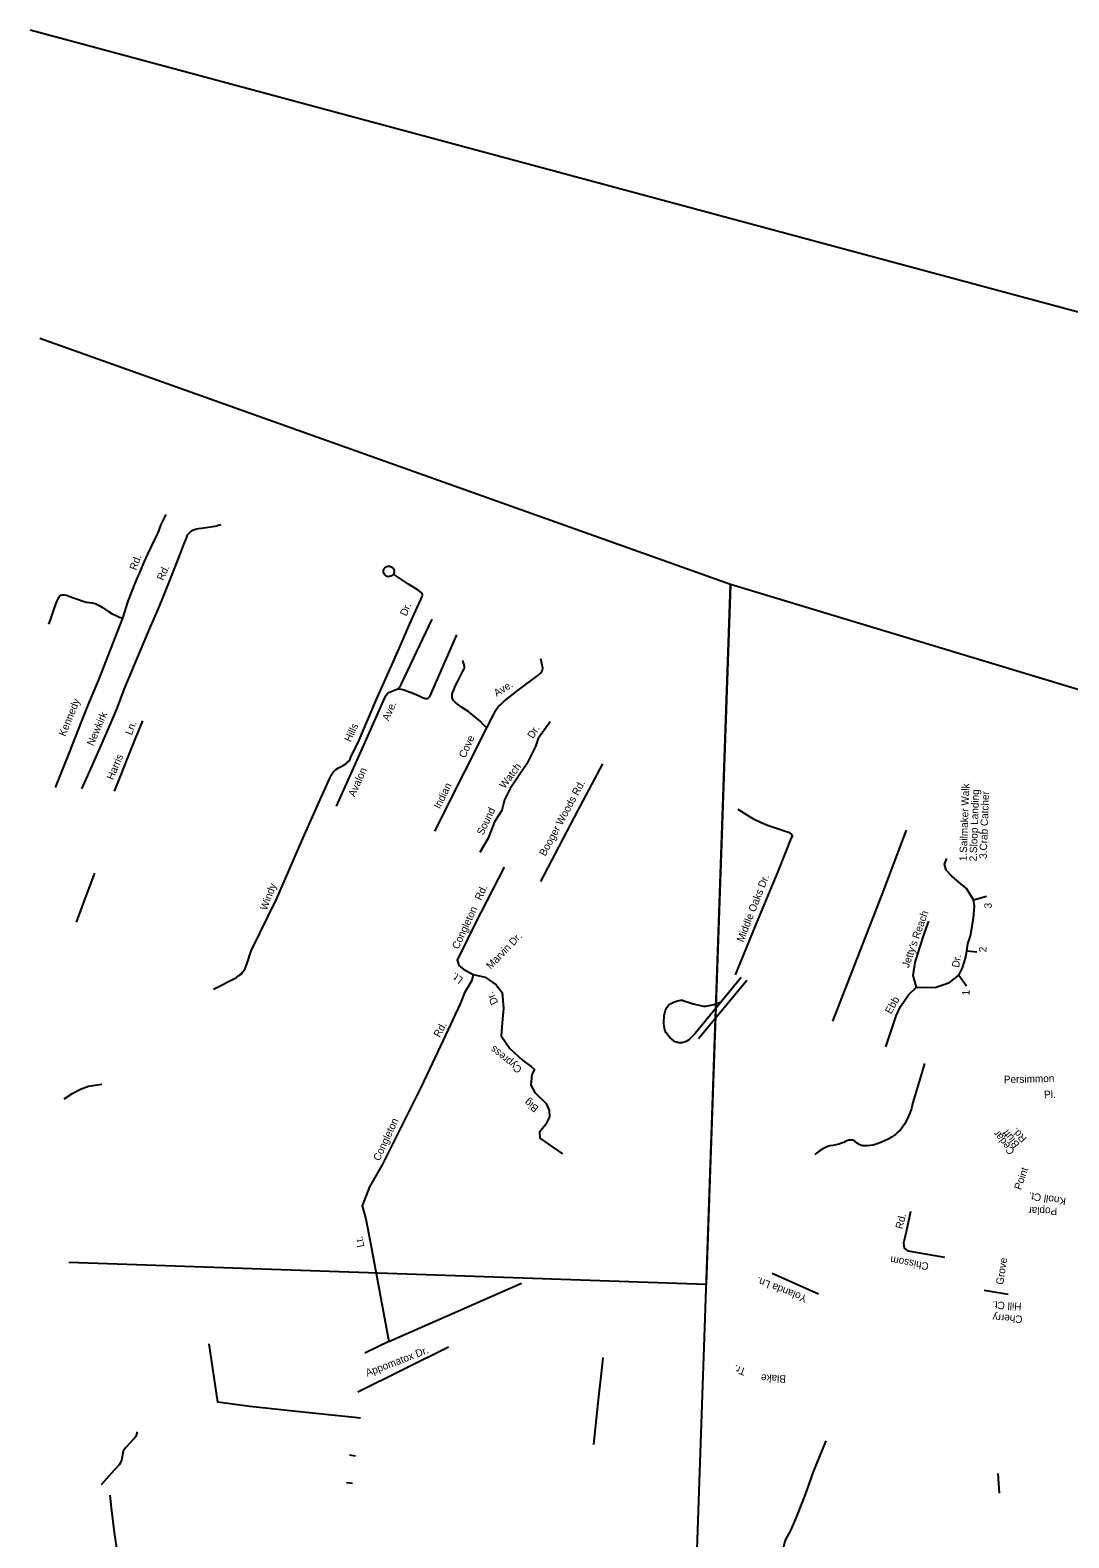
# Model space of a CAD drawing. Extents: x 2308163 to 2335412, y -96774 to 127732.
# Drawn here: x 2320522 to 2321093, y 33932 to 34759 of the extents above; entities that cross this region are included whole.
import ezdxf

# ---------------------------------------------------------------- set-up
doc = ezdxf.new("R2010")
doc.units = 0
for name, color, linetype in [('Old_Level_10', 7, 'Continuous'), ('Old_Level_35', 7, 'Continuous'), ('Old_Level_63', 7, 'Continuous')]:
    doc.layers.add(name, color=color, linetype=linetype)

msp = doc.modelspace()

# ---------------------------------------------------------------- linework, layer by layer
at = {"layer": 'Old_Level_35'}
for p, q in [((2320889.29, 34205.99), (2320915.81, 34237.99)), ((2320912.73, 34239.56), (2320901.77, 34226.2)), ((2320703.76, 33997.64), (2320700.4, 33997.97)), ((2320701, 33976.7), (2320697.76, 33977.28)), ((2321053.71, 33967.28), (2321054.37, 33956.49)), ((2320564.27, 33964.25), (2320561.35, 33961.01)), ((2320699.39, 33961.73), (2320696.15, 33962.06)), ((2320566.04, 33955.37), (2320566.63, 33950.28))]:
    msp.add_line(p, q, dxfattribs=at)
for points in [[(2320550.76, 34343.03), (2320555.7, 34354.07), (2320561.14, 34366.45), (2320566.32, 34378.22), (2320570.42, 34387.76), (2320573.97, 34397.51), (2320584.49, 34422.43), (2320588.52, 34431.96), (2320591.86, 34439.87), (2320594.96, 34447.4), (2320598.32, 34455.56), (2320601.42, 34463.49), (2320605.02, 34472.73), (2320606.74, 34477.1), (2320607.63, 34479.32), (2320608.34, 34481.17), (2320608.84, 34482.4), (2320609.62, 34483.39), (2320610.39, 34484.11), (2320611.66, 34484.96), (2320613.2, 34485.54), (2320614.83, 34485.9), (2320616.49, 34486.11), (2320618.95, 34486.41), (2320621.45, 34486.81), (2320622.7, 34487.06), (2320624.81, 34487.44), (2320625.69, 34487.69), (2320627.33, 34488.15)], [(2320573.27, 34436.76), (2320576.15, 34446.06), (2320579.11, 34453.47), (2320580.85, 34457.56), (2320583.16, 34463.13), (2320585.14, 34467.81), (2320586.9, 34471.9), (2320591, 34480.28), (2320592.61, 34483.51), (2320594.36, 34488.19), (2320597.02, 34493.64)], [(2320721.79, 34460.87), (2320721.38, 34460.35), (2320720.94, 34459.99), (2320720.41, 34459.68), (2320719.74, 34459.5), (2320719.06, 34459.48), (2320718.43, 34459.62), (2320717.93, 34459.84), (2320717.45, 34460.16), (2320717.08, 34460.55), (2320716.76, 34461.02), (2320716.56, 34461.43), (2320716.46, 34461.92), (2320716.41, 34462.42), (2320716.45, 34462.85), (2320716.56, 34463.35), (2320716.77, 34463.76), (2320717.05, 34464.19), (2320717.37, 34464.52), (2320717.74, 34464.83), (2320718.18, 34465.03), (2320718.58, 34465.18), (2320719.15, 34465.28), (2320719.7, 34465.25), (2320720.28, 34465.13), (2320720.72, 34464.93), (2320721.11, 34464.63), (2320721.39, 34464.41), (2320721.68, 34464.06), (2320721.9, 34463.73), (2320722.05, 34463.34), (2320722.16, 34462.91), (2320722.2, 34462.52), (2320722.21, 34462.07), (2320722.13, 34461.67), (2320722.01, 34461.27), (2320721.79, 34460.87)], [(2320680.39, 34334.22), (2320687.02, 34349.29), (2320687.81, 34350.79), (2320688.32, 34351.51), (2320688.82, 34352.25), (2320689.48, 34353), (2320690.25, 34353.72), (2320691.64, 34354.56), (2320694.18, 34355.89), (2320695.69, 34356.72), (2320696.32, 34357.23), (2320697.18, 34358.1), (2320698.01, 34359.41), (2320698.38, 34360.34), (2320702.98, 34369.67), (2320712.16, 34391.34), (2320721.55, 34412.17), (2320726.2, 34422.96), (2320730.68, 34433.24), (2320734.08, 34440.88), (2320736.81, 34447.03), (2320737.54, 34448.52), (2320737.71, 34449.32), (2320737.53, 34450.18), (2320737.07, 34450.75), (2320735.35, 34452.01), (2320730.17, 34455.3), (2320721.79, 34460.87)], [(2320532.65, 34433.41), (2320533.48, 34435.88), (2320535.36, 34441.34), (2320536.45, 34444.42), (2320537.18, 34446.27), (2320537.67, 34447.4), (2320538.18, 34448.27), (2320538.67, 34448.9), (2320539.16, 34449.27), (2320539.79, 34449.52), (2320540.22, 34449.57), (2320541.16, 34449.53), (2320542.41, 34449.29), (2320545.68, 34448.06), (2320549.4, 34446.7), (2320551.39, 34446), (2320553.36, 34445.45), (2320554.98, 34445.3), (2320556.44, 34445.12), (2320558.1, 34444.7), (2320559.21, 34444.29), (2320560.69, 34443.5), (2320562.19, 34442.52), (2320563.16, 34441.79), (2320565.36, 34440.35), (2320567.33, 34439.17), (2320569.55, 34438.11), (2320570.9, 34437.44), (2320573.27, 34436.76)], [(2320536.26, 34343.84), (2320543.91, 34363), (2320550.57, 34379.78), (2320554.91, 34390.79), (2320560.09, 34402.81), (2320573.27, 34436.76)], [(2320724.32, 34397.92), (2320725.12, 34398.8), (2320725.87, 34399.89), (2320726.28, 34400.76), (2320743.08, 34436.1)], [(2320724.32, 34397.92), (2320726.17, 34397.72), (2320727.69, 34397.34), (2320729.56, 34396.67), (2320733.03, 34395.34), (2320735.98, 34394.02), (2320738.22, 34392.94), (2320739.41, 34392.66), (2320740.34, 34392.65), (2320740.91, 34392.83), (2320741.3, 34393.08), (2320741.75, 34393.62), (2320742.13, 34394.36), (2320756.63, 34427.51)], [(2320773.21, 34376.48), (2320771.38, 34378.15), (2320769.42, 34380.09), (2320766.36, 34382.65), (2320763.17, 34385.24), (2320759.24, 34387.95), (2320756.77, 34389.63), (2320755.66, 34390.57), (2320755.06, 34391.31), (2320754.69, 34391.74), (2320754.21, 34392.57), (2320754.11, 34393.19), (2320754, 34393.97), (2320754.16, 34394.95), (2320754.54, 34396.08), (2320755.21, 34397.81), (2320755.78, 34399.3), (2320756.94, 34401.75), (2320758.4, 34404.73), (2320759.82, 34407.32), (2320760.61, 34408.92), (2320760.85, 34409.7), (2320760.89, 34410.42), (2320759.88, 34413.5)], [(2320773.21, 34376.48), (2320776.91, 34384.02), (2320778.08, 34386.24), (2320778.78, 34387.31), (2320779.61, 34388.25), (2320780.92, 34389.55), (2320782.57, 34391.14), (2320789.57, 34396.58), (2320801.05, 34405.33), (2320802.72, 34406.78), (2320803.25, 34407.46), (2320803.74, 34408.26), (2320803.92, 34409.26), (2320802.81, 34414.41)], [(2320690.5, 34333.47), (2320703.33, 34362.04), (2320717.07, 34392.98), (2320717.52, 34393.95), (2320717.8, 34394.36), (2320718.07, 34394.67), (2320718.43, 34395.1), (2320718.88, 34395.55), (2320719.15, 34395.76), (2320719.7, 34396.07), (2320724.32, 34397.92)], [(2320568.76, 34341.75), (2320571.74, 34349.39), (2320576.17, 34360.54), (2320579.87, 34369.68), (2320584.19, 34380.32)], [(2320807.84, 34379.78), (2320801.25, 34370.59), (2320799.84, 34366.25), (2320795.12, 34356.69), (2320789.49, 34348.41), (2320785.86, 34343.2), (2320782.82, 34337.03), (2320781.36, 34331.12), (2320777.38, 34324.98), (2320773.93, 34316), (2320769.24, 34308.01)], [(2320744.58, 34319.78), (2320760.87, 34352.15), (2320773.21, 34376.48)], [(2320802.81, 34292.24), (2320823.01, 34331.02), (2320836.9, 34356.69)], [(2320643.8, 34254.13), (2320657.77, 34282.86), (2320671.53, 34314.53), (2320680.39, 34334.22)], [(2320909.63, 34241.02), (2320920.79, 34268.13), (2320933.4, 34298.59), (2320940.47, 34316.05), (2320940.98, 34317.04), (2320940.62, 34317.91), (2320939.53, 34318.81), (2320938.28, 34319.21), (2320936.93, 34319.64), (2320934.44, 34320.57), (2320927.26, 34322.99), (2320925.88, 34323.4), (2320925.02, 34323.8), (2320923.04, 34324.71), (2320920.31, 34326.05), (2320917.6, 34327.6), (2320911.2, 34331.62)], [(2320963.03, 34215.46), (2320990.13, 34285.08), (2321003.48, 34320.28)], [(2320992.22, 34201.47), (2320997.79, 34218.34), (2321000.29, 34223.59), (2321004.69, 34229.93), (2321009.02, 34234.19), (2321019.23, 34234.07), (2321027.22, 34236.81), (2321032.23, 34240.81), (2321034.22, 34244.69), (2321036.05, 34250.66), (2321036.64, 34254.12), (2321037.24, 34258.04), (2321038.78, 34262.4), (2321040.28, 34272.09), (2321040.96, 34278.57), (2321040.39, 34282.07), (2321036.42, 34288.24), (2321032.37, 34291.86), (2321028.53, 34295.01), (2321025.39, 34298.36), (2321024.35, 34301.65), (2321025.62, 34304.85)], [(2320557.64, 34296.71), (2320552.63, 34283.28), (2320547.57, 34269.89)], [(2320782.7, 34300.04), (2320766.81, 34269.11), (2320758.84, 34253.03), (2320756.85, 34249.08), (2320757.67, 34245.97), (2320760.38, 34244.02), (2320765.53, 34241.07), (2320772.27, 34239.6), (2320778.31, 34235.38), (2320781.56, 34231.26), (2320782.19, 34222.59), (2320781.6, 34214.59), (2320781.05, 34207.51), (2320785.75, 34200.56), (2320792.64, 34194.15), (2320797.65, 34190.35)], [(2321040.39, 34282.07), (2321047.5, 34284.16)], [(2321009.02, 34234.19), (2321007.15, 34240.52), (2321008.32, 34247.67), (2321010.68, 34255.48), (2321013.54, 34264.43), (2321015.84, 34270.38)], [(2320623.08, 34233.15), (2320635.67, 34239.45), (2320637.01, 34240.49), (2320638.35, 34241.42), (2320639.03, 34242.38), (2320640.05, 34243.43), (2320641.49, 34247.41), (2320643.8, 34254.13)], [(2321036.64, 34254.12), (2321042.23, 34253.58)], [(2320765.53, 34241.07), (2320764.87, 34237.83), (2320760.94, 34231.07), (2320758.51, 34225.01), (2320749.21, 34205.15), (2320737, 34179.48), (2320715.57, 34136.67), (2320708.76, 34124.6), (2320704.7, 34114.16), (2320706.67, 34106.95), (2320710.02, 34089.86)], [(2321032.23, 34240.81), (2321036.56, 34234.84)], [(2320901.77, 34226.2), (2320887.59, 34208.79), (2320885.92, 34207.08), (2320884.63, 34205.86), (2320883.49, 34204.87), (2320882.65, 34204.31), (2320881.47, 34203.94), (2320880.2, 34203.67), (2320878.46, 34203.64), (2320877.35, 34203.9), (2320876.59, 34204.16), (2320874.86, 34205.38), (2320873.66, 34206.48), (2320872.65, 34207.6), (2320871.4, 34209.36), (2320870.88, 34210.81), (2320870.65, 34211.82), (2320870.56, 34212.7), (2320870.33, 34214.19), (2320870.28, 34215.79), (2320870.41, 34217.45), (2320870.57, 34218.7), (2320870.83, 34220.1), (2320871.27, 34221.47), (2320872, 34222.95), (2320872.45, 34223.78), (2320872.96, 34224.27), (2320873.98, 34224.99), (2320875.25, 34225.72), (2320877.27, 34226.42), (2320878.65, 34226.88), (2320879.65, 34227.09), (2320880.53, 34226.95), (2320881.89, 34226.55), (2320884.17, 34225.66), (2320886.4, 34224.93), (2320888.97, 34224.39), (2320891.12, 34223.93), (2320892.11, 34223.81), (2320893.46, 34223.78), (2320895.47, 34224.1), (2320898.37, 34224.91), (2320901.77, 34226.2)], [(2320797.65, 34190.35), (2320799.25, 34188.98), (2320797.92, 34186.25), (2320797.26, 34180.34), (2320799.43, 34176.32), (2320805.71, 34170.24), (2320807.43, 34166.48), (2320807.62, 34163.07), (2320805.31, 34158.52), (2320802.08, 34154.62), (2320802.27, 34151.22), (2320814.65, 34142.77)], [(2321013.51, 34192.24), (2321011.73, 34186.53), (2321010.5, 34182.43), (2321006.97, 34170.89), (2321006.27, 34167.53), (2321005.34, 34164.92), (2321004.53, 34162.95), (2321003.56, 34161.06), (2321002.44, 34159), (2321001.41, 34157.4), (2321000.24, 34155.91), (2320998.78, 34154.49), (2320997.43, 34153.24), (2320995.39, 34151.91), (2320993.44, 34150.8), (2320991.5, 34149.8), (2320989.5, 34148.89), (2320987.53, 34148.1), (2320985.26, 34147.48), (2320983.66, 34147.24), (2320981.78, 34147.11), (2320980.82, 34147.09), (2320979.65, 34147.16), (2320978.52, 34147.44), (2320977.99, 34147.69)], [(2320561.75, 34180.8), (2320554.48, 34179.56), (2320550.02, 34178.02), (2320545.08, 34175.51), (2320540.86, 34172.63)], [(2320977.99, 34147.69), (2320977.45, 34147.93), (2320976.42, 34148.62), (2320975.27, 34149.58), (2320974.73, 34149.86), (2320974.1, 34150.09), (2320973.09, 34150.2), (2320971.84, 34150.11), (2320970.7, 34149.74), (2320969.06, 34148.91), (2320967.79, 34148.45), (2320966.44, 34148.04), (2320964.66, 34147.64), (2320963.15, 34147.3), (2320961.51, 34146.99), (2320959.4, 34146.3), (2320957.6, 34145.45), (2320955.68, 34144.11), (2320954.15, 34143.04), (2320953.13, 34142.17)], [(2321005.69, 34111.08), (2321003.35, 34099.93), (2321001.91, 34093.63), (2321002.31, 34090.93), (2321004.21, 34089.4), (2321024.37, 34086.02)], [(2320710.02, 34089.86), (2320719.37, 34039.68), (2320706.1, 34033.24)], [(2320929.73, 34077.13), (2320955.14, 34065.88)], [(2320719.37, 34039.68), (2320792.13, 34071.62)], [(2321059.46, 34065.41), (2321046.18, 34067.58)], [(2320700.4, 33997.97), (2320670.34, 34001.08), (2320643.02, 34003.98), (2320625.42, 34006.29), (2320620.59, 34038.4)], [(2320702.36, 34012.07), (2320752.06, 34036.72)], [(2320836.89, 34030.95), (2320836.46, 34027.27), (2320834.02, 34006), (2320831.72, 33983.16)], [(2320581.15, 33990.08), (2320580.42, 33987.45), (2320577.3, 33984.05), (2320574.69, 33981.29), (2320573.45, 33979.42), (2320572.98, 33976.43), (2320572.49, 33974.42), (2320571.26, 33972.03), (2320568.52, 33969.03), (2320564.27, 33964.25)], [(2320936.05, 33926.31), (2320936.5, 33928.82), (2320937.33, 33931.06), (2320939.96, 33935.88), (2320943.25, 33943.52), (2320948.02, 33955.65), (2320952.42, 33968.16), (2320959.44, 33985.12)], [(2320566.63, 33950.28), (2320566.87, 33948.27), (2320568.55, 33934.8), (2320570.63, 33920.17), (2320571.81, 33910.44), (2320571.7, 33907.18), (2320570.47, 33904.06), (2320567.5, 33899.92), (2320564.38, 33896.77)]]:
    msp.add_lwpolyline(points, dxfattribs=at)
at = {"layer": 'Old_Level_63'}
for p, q in [((2320906.85, 34455.15), (2320527.71, 34590.21)), ((2321414.95, 34301.9), (2320906.85, 34455.15))]:
    msp.add_line(p, q, dxfattribs=at)
for points in [[(2322212.45, 34280.74), (2322047.32, 34349.18), (2320522.37, 34759.49)], [(2320906.85, 34455.05), (2320893.6, 34070.87), (2320543.69, 34082.94)], [(2321414.95, 34301.9), (2321386.61, 33480.39), (2320873.79, 33496.58), (2320906.85, 34455.15)]]:
    msp.add_lwpolyline(points, dxfattribs=at)

# ---------------------------------------------------------------- texts
at = {"layer": 'Old_Level_10'}
for s, height, rotation, p in [('Rd.', 4.101, 69.61666, (2320580.6, 34462.71)), ('Rd.', 4.101, 65.08465, (2320595.4, 34457.03)), ('Dr.', 4.101, 67.31688, (2320729.01, 34437.54)), ('Ave.', 4.101, 32.04993, (2320778.54, 34393.47)), ('Kennedy', 4.101, 67.84666, (2320541.64, 34371.5)), ('Ave.', 4.101, 66.05059, (2320719.16, 34380)), ('Newkirk', 4.101, 66.49904, (2320557.06, 34366.29)), ('Ln.', 4.101, 69.1108, (2320578.17, 34372.2)), ('Hills', 4.101, 65.64113, (2320698.4, 34368.46)), ('Cove', 4.101, 65.514, (2320761.26, 34359.63)), ('Dr.', 4.101, 57.31714, (2320798.48, 34370.28)), ('Harris', 4.101, 67.33071, (2320567.96, 34347.6)), ('Avalon', 4.101, 65.81929, (2320700.52, 34338.27)), ('Watch', 4.101, 53.11391, (2320782.92, 34342.83)), ('Indian ', 4.101, 63.79948, (2320747.38, 34331.71)), ('Booger Woods Rd.', 4.101, 61.62421, (2320805.23, 34305.73)), ('1.Sailmaker Walk', 4.101, 88.02472, (2321036.61, 34303.27)), ('2.Sloop Landing', 4.101, 88.02472, (2321042.11, 34303.12)), ('3.Crab Catcher', 4.101, 88.02472, (2321047.61, 34304.56)), ('Sound ', 4.101, 64.33474, (2320771.07, 34317.24)), ('Windy', 4.101, 69.47857, (2320652.33, 34276)), ('Congleton   Rd.', 4.101, 64.9615, (2320757.47, 34254.67)), ('Middle Oaks Dr.', 4.101, 68.76325, (2320913.98, 34258.55)), ('3', 4.1, 88.02472, (2321050.32, 34277.33)), ("Jetty's Reach", 4.101, 70.51059, (2321004.74, 34244.44)), ('Marvin Dr.', 4.101, 45.82336, (2320775.24, 34243.72)), ('2', 4.1, 88.02472, (2321047.42, 34253.28)), ('Dr.', 4.101, 80.23905, (2321032.38, 34244.67)), ('Lt.', 4.101, 143.65228, (2320760.45, 34238.96)), ('Dr.', 4.101, 115.51581, (2320779.43, 34225.64)), ('1', 4.1, 88.02472, (2321038.12, 34229.56)), ('Ebb ', 4.101, 60.32335, (2320995.04, 34219.09)), ('Rd.', 4.101, 61.53773, (2320747.19, 34206.24)), ('Cypress', 4.101, 140.96632, (2320792.78, 34189.67)), ('Persimmon ', 4.101, 1.50763, (2321057.05, 34181.44)), ('Big', 4.101, 141.47213, (2320801.93, 34168.33)), ('Pl.', 4.101, 1.50763, (2321079.11, 34173.21)), ('Congleton', 4.101, 64.94126, (2320714.17, 34138.44)), ('Bluff', 4.101, 128.34841, (2321065.87, 34147.88)), ('Rd.', 4.101, 134.77371, (2321069.84, 34151.37)), ('Cedar ', 4.101, 128.34841, (2321063.26, 34144.18)), ('Point', 4.101, 71.00177, (2321066.38, 34122.59)), ('Poplar', 4.101, 178.55333, (2321086.36, 34113.13)), ('Knoll Ct.', 4.101, 171.48595, (2321091.34, 34118.52)), ('Rd.', 4.101, 75.37758, (2321001.31, 34101.09)), ('Lt. ', 4.101, 101.44828, (2320705.94, 34091.77)), ('Chissom', 4.101, 169.62556, (2321016.05, 34082.75)), ('Grove ', 4.101, 81.46465, (2321056.65, 34070.62)), ('Yolanda Ln.', 4.101, 158.64024, (2320949.32, 34064.63)), ('Cherry ', 4.101, 176.19754, (2321067.36, 34053.8)), ('Hill Ct.', 4.101, 176.19754, (2321066.8, 34060.72)), ('Appomatox Dr.', 4.101, 20.8983, (2320707.47, 34020.38)), ('Tr.', 4.101, 159.60338, (2320915.81, 34024.67)), ('Blake', 4.101, 177.56817, (2320937.43, 34021.09))]:
    msp.add_text(s, height=height, rotation=rotation, dxfattribs=at).set_placement(p)

doc.saveas('drawing.dxf')
